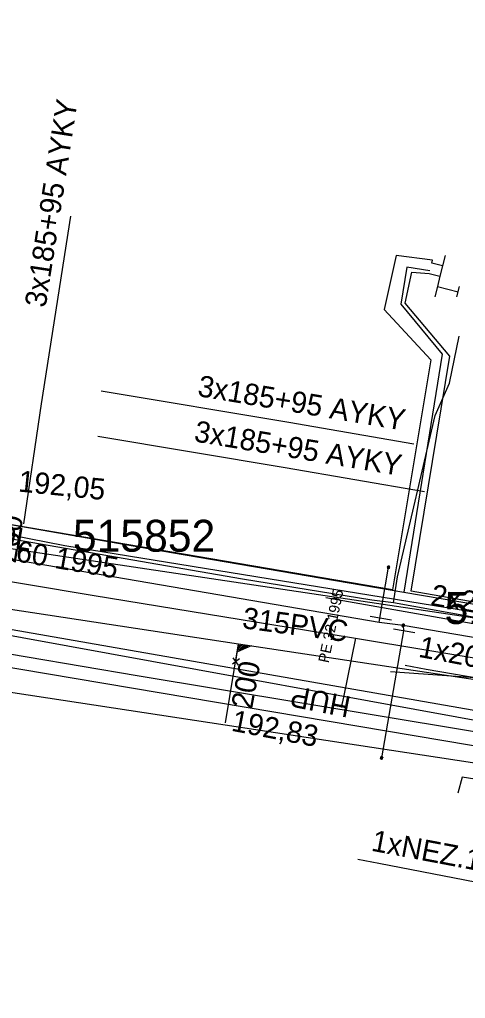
# Model space of a CAD drawing. Extents: x -746464 to -745690, y -1051581 to -1049993.
# Drawn here: x -746173.2 to -746152.23, y -1050974.15 to -1050928.11 of the extents above; entities that cross this region are included whole.
import ezdxf

# ---------------------------------------------------------------- set-up
doc = ezdxf.new("R2010")
doc.units = 0
for name, color, linetype in [('04_CETIN_neprovozovane', 7, 'Continuous'), ('04_CETIN_NN', 7, 'Continuous'), ('04_CETIN_sdelovaci_podzem', 7, 'Continuous'), ('37_TVNET_sdelovaci_televizni kabely', 7, 'Continuous'), ('45_Eltodo_popisy', 7, 'Continuous'), ('45_Eltodo_vedeni_NN_zemni', 7, 'Continuous'), ('48_Prazs_plynarenska_STL', 7, 'Continuous'), ('48_Prazs_plynarenska_STL_popisy', 7, 'Continuous'), ('51_PVaK_kanal_jednotna_neoverena poloha_pripojka', 7, 'Continuous'), ('51_PVaK_kanal_jednotna_overena poloha_rad', 7, 'Continuous'), ('51_PVaK_kanal_objekty', 7, 'Continuous'), ('51_PVaK_kanal_popisy', 7, 'Continuous'), ('51_PVaK_vodovod_chranicky_objekty', 7, 'Continuous'), ('51_PVaK_vodovod_NEPROVOZUJE PVK_neoverene poloha', 7, 'Continuous'), ('51_PVaK_vodovod_NEPROVOZUJE PVK_overena poloha', 7, 'Continuous'), ('51_PVaK_vodovod_overena poloha_rad', 7, 'Continuous'), ('51_PVaK_vodovod_popisy', 7, 'Continuous'), ('51_PVaK_vodovod_zruseno_overena poloha', 7, 'Continuous'), ('55_PREdi_NN', 7, 'Continuous'), ('55_PREdi_NN_popisy', 7, 'Continuous'), ('55_PREdi_NN_pripojovaci_misto', 7, 'Continuous'), ('55_PREdi_stavby_popisy', 7, 'Continuous')]:
    doc.layers.add(name, color=color, linetype=linetype)

msp = doc.modelspace()

# ---------------------------------------------------------------- linework, layer by layer
at = {"layer": '04_CETIN_neprovozovane'}
msp.add_lwpolyline([(-746094.33, -1051018.57), (-746121.85, -1051017.38), (-746125.81, -1051016.41), (-746128.7, -1051014.1), (-746129.76, -1051011.59), (-746132.33, -1050984.4), (-746132.27, -1050974.78), (-746131.85, -1050965.18), (-746132.29, -1050965.1), (-746139.52, -1050963.68), (-746140.75, -1050963.44), (-746167.67, -1050958.97)], dxfattribs=at)
at = {"layer": '04_CETIN_NN'}
msp.add_lwpolyline([(-746178.55, -1050957.75), (-746149.35, -1050962.67)], dxfattribs=at)
at = {"layer": '04_CETIN_sdelovaci_podzem'}
for points in [[(-746155.61, -1050955.54), (-746155.43, -1050954.32), (-746153.66, -1050946.74), (-746152.98, -1050945.22), (-746152.53, -1050943)], [(-746155.61, -1050955.54), (-746156.64, -1050955.42), (-746162.72, -1050954.43), (-746178.2, -1050951.75)], [(-746156.64, -1050955.42), (-746162.72, -1050954.43)], [(-746143.87, -1050957.66), (-746155.61, -1050955.54)], [(-746167.67, -1050958.97), (-746178.03, -1050957.22), (-746181.63, -1050957.52)], [(-746178.55, -1050957.75), (-746149.35, -1050962.67)], [(-746149.35, -1050962.67), (-746149.5, -1050963.7), (-746149.91, -1050964.13), (-746152.39, -1050963.75), (-746152.59, -1050964.5)]]:
    msp.add_lwpolyline(points, dxfattribs=at)
at = {"layer": '37_TVNET_sdelovaci_televizni kabely'}
msp.add_line((-746181.624, -1050958.53), (-746140.499, -1050964.785), dxfattribs=at)
msp.add_lwpolyline([(-746179.6, -1050952.103), (-746140.684, -1050957.917), (-746140.028, -1050940.845), (-746146.921, -1050940.58)], dxfattribs=at)
at = {"layer": '45_Eltodo_vedeni_NN_zemni'}
for points in [[(-746171.077, -1050952.859), (-746193.71, -1050948.42)], [(-746149.539, -1050956.363), (-746171.077, -1050952.859)]]:
    msp.add_lwpolyline(points, dxfattribs=at)
at = {"layer": '48_Prazs_plynarenska_STL'}
for points in [[(-746223.4, -1050946.22), (-746203.02, -1050949.53), (-746187.08, -1050952.24), (-746178.97, -1050953.64), (-746169.78, -1050955.18), (-746157.4, -1050957.2), (-746140.96, -1050959.93), (-746135.46, -1050960.65)], [(-746157.4, -1050957.2), (-746157.969, -1050959.979)], [(-746157.969, -1050959.979), (-746158.068, -1050960.467)]]:
    msp.add_lwpolyline(points, dxfattribs=at)
at = {"layer": '51_PVaK_kanal_jednotna_neoverena poloha_pripojka'}
msp.add_line((-746163.52, -1050961.19), (-746162.901, -1050957.471), dxfattribs=at)
at = {"layer": '51_PVaK_kanal_jednotna_overena poloha_rad'}
msp.add_lwpolyline([(-746183.62, -1050954.34), (-746174.568, -1050955.708), (-746162.901, -1050957.471), (-746142.73, -1050960.52)], dxfattribs=at)
at = {"layer": '51_PVaK_kanal_objekty'}
for p, q in [((-746162.852, -1050958.176), (-746163.186, -1050958.425)), ((-746162.905, -1050958.473), (-746163.155, -1050958.134))]:
    msp.add_line(p, q, dxfattribs=at)
for points in [[(-746163.026, -1050958.306), (-746162.9, -1050957.473), (-746162.306, -1050957.563), (-746162.957, -1050957.849)], [(-746162.901, -1050957.772), (-746162.864, -1050957.53), (-746162.484, -1050957.587), (-746162.905, -1050957.772)], [(-746162.844, -1050957.691), (-746162.825, -1050957.57), (-746162.63, -1050957.599), (-746162.848, -1050957.691)]]:
    msp.add_lwpolyline(points, dxfattribs=at)
at = {"layer": '51_PVaK_vodovod_chranicky_objekty'}
for p, q in [((-746155.906, -1050953.913), (-746155.79, -1050953.831)), ((-746155.906, -1050953.913), (-746155.902, -1050953.893)), ((-746155.906, -1050953.913), (-746155.886, -1050953.916)), ((-746155.889, -1050953.814), (-746155.892, -1050953.834)), ((-746155.807, -1050953.929), (-746155.889, -1050953.814)), ((-746155.889, -1050953.814), (-746155.869, -1050953.818)), ((-746155.807, -1050953.929), (-746155.827, -1050953.926)), ((-746155.79, -1050953.831), (-746155.81, -1050953.828)), ((-746155.807, -1050953.929), (-746155.804, -1050953.91)), ((-746155.79, -1050953.831), (-746155.794, -1050953.851)), ((-746155.71, -1050956.361), (-746156.71, -1050956.193)), ((-746154.61, -1050956.948), (-746155.61, -1050956.785)), ((-746155.205, -1050956.655), (-746155.105, -1050956.555)), ((-746155.205, -1050956.555), (-746155.105, -1050956.655)), ((-746155.205, -1050956.555), (-746155.205, -1050956.575)), ((-746155.205, -1050956.555), (-746155.185, -1050956.555)), ((-746155.205, -1050956.655), (-746155.205, -1050956.635)), ((-746155.205, -1050956.655), (-746155.185, -1050956.655)), ((-746155.105, -1050956.555), (-746155.125, -1050956.555)), ((-746155.105, -1050956.655), (-746155.125, -1050956.655)), ((-746155.105, -1050956.555), (-746155.105, -1050956.575)), ((-746155.105, -1050956.655), (-746155.105, -1050956.635)), ((-746156.215, -1050962.782), (-746156.218, -1050962.802)), ((-746156.133, -1050962.897), (-746156.215, -1050962.782)), ((-746156.215, -1050962.782), (-746156.195, -1050962.786)), ((-746156.231, -1050962.881), (-746156.116, -1050962.799)), ((-746156.231, -1050962.881), (-746156.228, -1050962.861)), ((-746156.231, -1050962.881), (-746156.211, -1050962.884)), ((-746156.133, -1050962.897), (-746156.152, -1050962.894)), ((-746156.116, -1050962.799), (-746156.136, -1050962.795)), ((-746156.133, -1050962.897), (-746156.129, -1050962.878)), ((-746156.116, -1050962.799), (-746156.12, -1050962.818))]:
    msp.add_line(p, q, dxfattribs=at)
for points in [[(-746155.84, -1050953.823), (-746155.845, -1050953.822), (-746155.85, -1050953.822), (-746155.855, -1050953.822), (-746155.86, -1050953.823), (-746155.866, -1050953.825), (-746155.87, -1050953.828), (-746155.874, -1050953.83), (-746155.879, -1050953.833), (-746155.883, -1050953.837), (-746155.886, -1050953.84), (-746155.89, -1050953.844), (-746155.893, -1050953.849), (-746155.895, -1050953.854), (-746155.896, -1050953.859), (-746155.897, -1050953.864), (-746155.898, -1050953.868), (-746155.898, -1050953.874), (-746155.898, -1050953.879), (-746155.897, -1050953.884), (-746155.895, -1050953.889), (-746155.892, -1050953.894), (-746155.89, -1050953.898), (-746155.887, -1050953.903), (-746155.883, -1050953.906), (-746155.88, -1050953.91), (-746155.875, -1050953.914), (-746155.871, -1050953.917), (-746155.866, -1050953.919), (-746155.861, -1050953.92), (-746155.856, -1050953.921), (-746155.851, -1050953.922), (-746155.846, -1050953.922), (-746155.841, -1050953.922), (-746155.836, -1050953.921), (-746155.83, -1050953.918), (-746155.826, -1050953.916), (-746155.822, -1050953.914), (-746155.817, -1050953.911), (-746155.813, -1050953.907), (-746155.81, -1050953.904), (-746155.806, -1050953.899), (-746155.803, -1050953.895), (-746155.801, -1050953.89), (-746155.8, -1050953.885), (-746155.799, -1050953.88), (-746155.798, -1050953.875), (-746155.798, -1050953.87), (-746155.798, -1050953.865), (-746155.799, -1050953.86), (-746155.801, -1050953.854), (-746155.804, -1050953.85), (-746155.806, -1050953.845), (-746155.809, -1050953.841), (-746155.813, -1050953.837), (-746155.816, -1050953.834), (-746155.821, -1050953.83), (-746155.825, -1050953.827), (-746155.83, -1050953.825), (-746155.835, -1050953.823), (-746155.84, -1050953.823)], [(-746155.105, -1050956.605), (-746155.105, -1050956.6), (-746155.106, -1050956.595), (-746155.107, -1050956.59), (-746155.109, -1050956.585), (-746155.112, -1050956.58), (-746155.115, -1050956.576), (-746155.118, -1050956.572), (-746155.122, -1050956.568), (-746155.126, -1050956.565), (-746155.13, -1050956.562), (-746155.135, -1050956.559), (-746155.14, -1050956.557), (-746155.145, -1050956.556), (-746155.15, -1050956.555), (-746155.155, -1050956.555), (-746155.16, -1050956.555), (-746155.165, -1050956.556), (-746155.17, -1050956.557), (-746155.175, -1050956.559), (-746155.18, -1050956.562), (-746155.184, -1050956.565), (-746155.188, -1050956.568), (-746155.192, -1050956.572), (-746155.195, -1050956.576), (-746155.198, -1050956.58), (-746155.201, -1050956.585), (-746155.203, -1050956.59), (-746155.204, -1050956.595), (-746155.205, -1050956.6), (-746155.205, -1050956.605), (-746155.205, -1050956.61), (-746155.204, -1050956.615), (-746155.203, -1050956.62), (-746155.201, -1050956.625), (-746155.198, -1050956.63), (-746155.195, -1050956.634), (-746155.192, -1050956.638), (-746155.188, -1050956.642), (-746155.184, -1050956.645), (-746155.18, -1050956.648), (-746155.175, -1050956.651), (-746155.17, -1050956.653), (-746155.165, -1050956.654), (-746155.16, -1050956.655), (-746155.155, -1050956.655), (-746155.15, -1050956.655), (-746155.145, -1050956.654), (-746155.14, -1050956.653), (-746155.135, -1050956.651), (-746155.13, -1050956.648), (-746155.126, -1050956.645), (-746155.122, -1050956.642), (-746155.118, -1050956.638), (-746155.115, -1050956.634), (-746155.112, -1050956.63), (-746155.109, -1050956.625), (-746155.107, -1050956.62), (-746155.106, -1050956.615), (-746155.105, -1050956.61), (-746155.105, -1050956.605)], [(-746156.166, -1050962.791), (-746156.171, -1050962.79), (-746156.176, -1050962.79), (-746156.181, -1050962.79), (-746156.186, -1050962.791), (-746156.192, -1050962.793), (-746156.196, -1050962.796), (-746156.2, -1050962.798), (-746156.205, -1050962.801), (-746156.209, -1050962.805), (-746156.212, -1050962.808), (-746156.216, -1050962.813), (-746156.219, -1050962.817), (-746156.221, -1050962.822), (-746156.222, -1050962.827), (-746156.223, -1050962.832), (-746156.224, -1050962.837), (-746156.224, -1050962.842), (-746156.224, -1050962.847), (-746156.222, -1050962.852), (-746156.22, -1050962.858), (-746156.218, -1050962.862), (-746156.216, -1050962.866), (-746156.212, -1050962.871), (-746156.209, -1050962.875), (-746156.205, -1050962.878), (-746156.201, -1050962.882), (-746156.196, -1050962.885), (-746156.192, -1050962.887), (-746156.187, -1050962.888), (-746156.182, -1050962.889), (-746156.177, -1050962.89), (-746156.172, -1050962.89), (-746156.167, -1050962.89), (-746156.161, -1050962.888), (-746156.156, -1050962.886), (-746156.152, -1050962.884), (-746156.147, -1050962.882), (-746156.143, -1050962.878), (-746156.139, -1050962.875), (-746156.135, -1050962.871), (-746156.132, -1050962.867), (-746156.129, -1050962.862), (-746156.127, -1050962.858), (-746156.125, -1050962.853), (-746156.124, -1050962.848), (-746156.124, -1050962.843), (-746156.124, -1050962.838), (-746156.124, -1050962.833), (-746156.125, -1050962.828), (-746156.127, -1050962.822), (-746156.13, -1050962.818), (-746156.132, -1050962.813), (-746156.135, -1050962.809), (-746156.139, -1050962.805), (-746156.142, -1050962.801), (-746156.147, -1050962.798), (-746156.151, -1050962.795), (-746156.156, -1050962.793), (-746156.161, -1050962.791), (-746156.166, -1050962.791)]]:
    msp.add_lwpolyline(points, dxfattribs=at)
at = {"layer": '51_PVaK_vodovod_NEPROVOZUJE PVK_neoverene poloha'}
for p, q in [((-746156.25, -1050956.27), (-746155.847, -1050953.873)), ((-746156.283, -1050956.467), (-746156.25, -1050956.27))]:
    msp.add_line(p, q, dxfattribs=at)
for points in [[(-746131.754, -1050898.624), (-746138.364, -1050959.474), (-746155.156, -1050956.606)], [(-746155.156, -1050956.606), (-746156.283, -1050956.467), (-746181.72, -1050952.118), (-746198.444, -1050949.286), (-746201.26, -1050948.77)]]:
    msp.add_lwpolyline(points, dxfattribs=at)
at = {"layer": '51_PVaK_vodovod_NEPROVOZUJE PVK_overena poloha'}
for p, q in [((-746155.156, -1050956.606), (-746155.15, -1050956.86)), ((-746155.15, -1050956.86), (-746156.173, -1050962.841))]:
    msp.add_line(p, q, dxfattribs=at)
at = {"layer": '51_PVaK_vodovod_overena poloha_rad'}
msp.add_lwpolyline([(-746042.7, -1051019.92), (-746042.94, -1051019.91), (-746043.12, -1051019.91), (-746062.01, -1051019.53), (-746073.53, -1051019.56), (-746091.39, -1051018.74), (-746129.45, -1051017.12), (-746129.85, -1051017.08), (-746132.44, -1051014.95), (-746132.41, -1051014.45), (-746131.88, -1050978.37), (-746130.6, -1050966.48), (-746130.53, -1050965.33), (-746131.39, -1050964.15), (-746150.56, -1050960.82), (-746178.86, -1050955.89), (-746201.61, -1050952.53), (-746201.83, -1050952.49)], dxfattribs=at)
at = {"layer": '51_PVaK_vodovod_zruseno_overena poloha'}
msp.add_lwpolyline([(-746129.55, -1050965.2), (-746136.31, -1050963.9), (-746201.6, -1050951.98)], dxfattribs=at)
at = {"layer": '55_PREdi_NN'}
for points in [[(-746153.305, -1050939.701), (-746153.812, -1050939.574), (-746153.776, -1050939.427), (-746155.486, -1050939.203), (-746156.047, -1050941.755), (-746153.86, -1050944.11), (-746155.655, -1050954.933), (-746177.357, -1050951.231), (-746177.234, -1050950.509)], [(-746153.184, -1050939.216), (-746153.305, -1050939.701), (-746153.427, -1050940.185), (-746153.548, -1050940.67), (-746153.67, -1050941.156)], [(-746153.908, -1050939.933), (-746154.981, -1050939.76), (-746155.262, -1050941.501), (-746153.323, -1050943.854), (-746155.124, -1050955.037)], [(-746150.955, -1050963.904), (-746150.807, -1050962.894), (-746150.341, -1050962.117), (-746141.237, -1050963.479), (-746140.843, -1050957.423), (-746154.785, -1050955.003), (-746152.962, -1050943.942), (-746155.066, -1050941.446), (-746154.757, -1050939.988), (-746153.934, -1050940.058), (-746153.427, -1050940.185)], [(-746153.548, -1050940.67), (-746153.063, -1050940.792)], [(-746221.26, -1050943.74), (-746202.514, -1050946.953), (-746187.107, -1050949.54), (-746184.174, -1050950.033), (-746166.055, -1050953.183), (-746155.124, -1050955.037)], [(-746155.124, -1050955.037), (-746139.963, -1050957.608)]]:
    msp.add_lwpolyline(points, dxfattribs=at)
at = {"layer": '55_PREdi_NN_popisy'}
for points in [[(-746173.006, -1050951.828), (-746172.165, -1050946.182), (-746170.796, -1050937.352)], [(-746169.354, -1050945.568), (-746160.542, -1050947.048), (-746154.661, -1050948.07)], [(-746169.522, -1050947.699), (-746160.709, -1050949.178), (-746154.156, -1050950.313)]]:
    msp.add_lwpolyline(points, dxfattribs=at)
at = {"layer": '55_PREdi_NN_pripojovaci_misto'}
for p, q in [((-746152.638, -1050941.156), (-746152.517, -1050940.67)), ((-746153.063, -1050940.792), (-746152.578, -1050940.913))]:
    msp.add_line(p, q, dxfattribs=at)
at = {"layer": '55_PREdi_stavby_popisy'}
for points in [[(-746158.8, -1050955.292), (-746149.202, -1050956.979), (-746140.195, -1050958.845)], [(-746155.064, -1050958.477), (-746154.081, -1050958.662), (-746140.867, -1050960.924)], [(-746155.747, -1050958.778), (-746146.71, -1050959.418), (-746140.713, -1050959.877)], [(-746157.284, -1050967.595), (-746156.302, -1050967.78), (-746142.155, -1050970.538)]]:
    msp.add_lwpolyline(points, dxfattribs=at)

# ---------------------------------------------------------------- texts
at = {"layer": '45_Eltodo_popisy'}
for s, p in [('515852', (-746170.69, -1050953.14)), ('515851', (-746153.21, -1050956.54))]:
    msp.add_text(s, height=1.5, dxfattribs=at).set_placement(p)
at = {"layer": '48_Prazs_plynarenska_STL_popisy'}
for s, height, rotation, p in [('STL PE 160 1995', 1, 350.2058, (-746179.058, -1050952.61)), ('PE 32 1995', 0.5, 78.4286, (-746158.666, -1050958.396)), ('HUP', 1, 169, (-746157.568, -1050959.967))]:
    msp.add_text(s, height=height, rotation=rotation, dxfattribs=at).set_placement(p)
at = {"layer": '51_PVaK_kanal_popisy'}
for s, rotation, p in [('192,05', 354.2739, (-746173.289, -1050950.306)), ('200', 80.5274, (-746173.386, -1050953.712)), ('315PVC', 352.4063, (-746162.762, -1050956.733)), ('200', 79.5495, (-746162.27, -1050960.584)), ('192,83', 349.0934, (-746163.281, -1050961.554))]:
    msp.add_text(s, height=1, rotation=rotation, dxfattribs=at).set_placement(p)
at = {"layer": '51_PVaK_vodovod_popisy'}
msp.add_text('100L', height=1, rotation=350.7353, dxfattribs=at).set_placement((-746175.656, -1050952.623))
at = {"layer": '55_PREdi_NN_popisy'}
for rotation, p in [(81.1854, (-746171.975, -1050941.69)), (350.4688, (-746164.865, -1050945.815)), (350.4724, (-746165.033, -1050947.946))]:
    msp.add_text('3x185+95 AYKY', height=1, rotation=rotation, dxfattribs=at).set_placement(p)
at = {"layer": '55_PREdi_stavby_popisy'}
for s, rotation, p in [('2x20-15.0mBet. r.', 350.0322, (-746153.914, -1050955.643)), ('1x200-8,8mPVC', 349.3284, (-746154.48, -1050958.078)), ('1xNEZ.17,2mTK2', 349.3278, (-746156.7, -1050967.196))]:
    msp.add_text(s, height=1, rotation=rotation, dxfattribs=at).set_placement(p)

doc.saveas('drawing.dxf')
